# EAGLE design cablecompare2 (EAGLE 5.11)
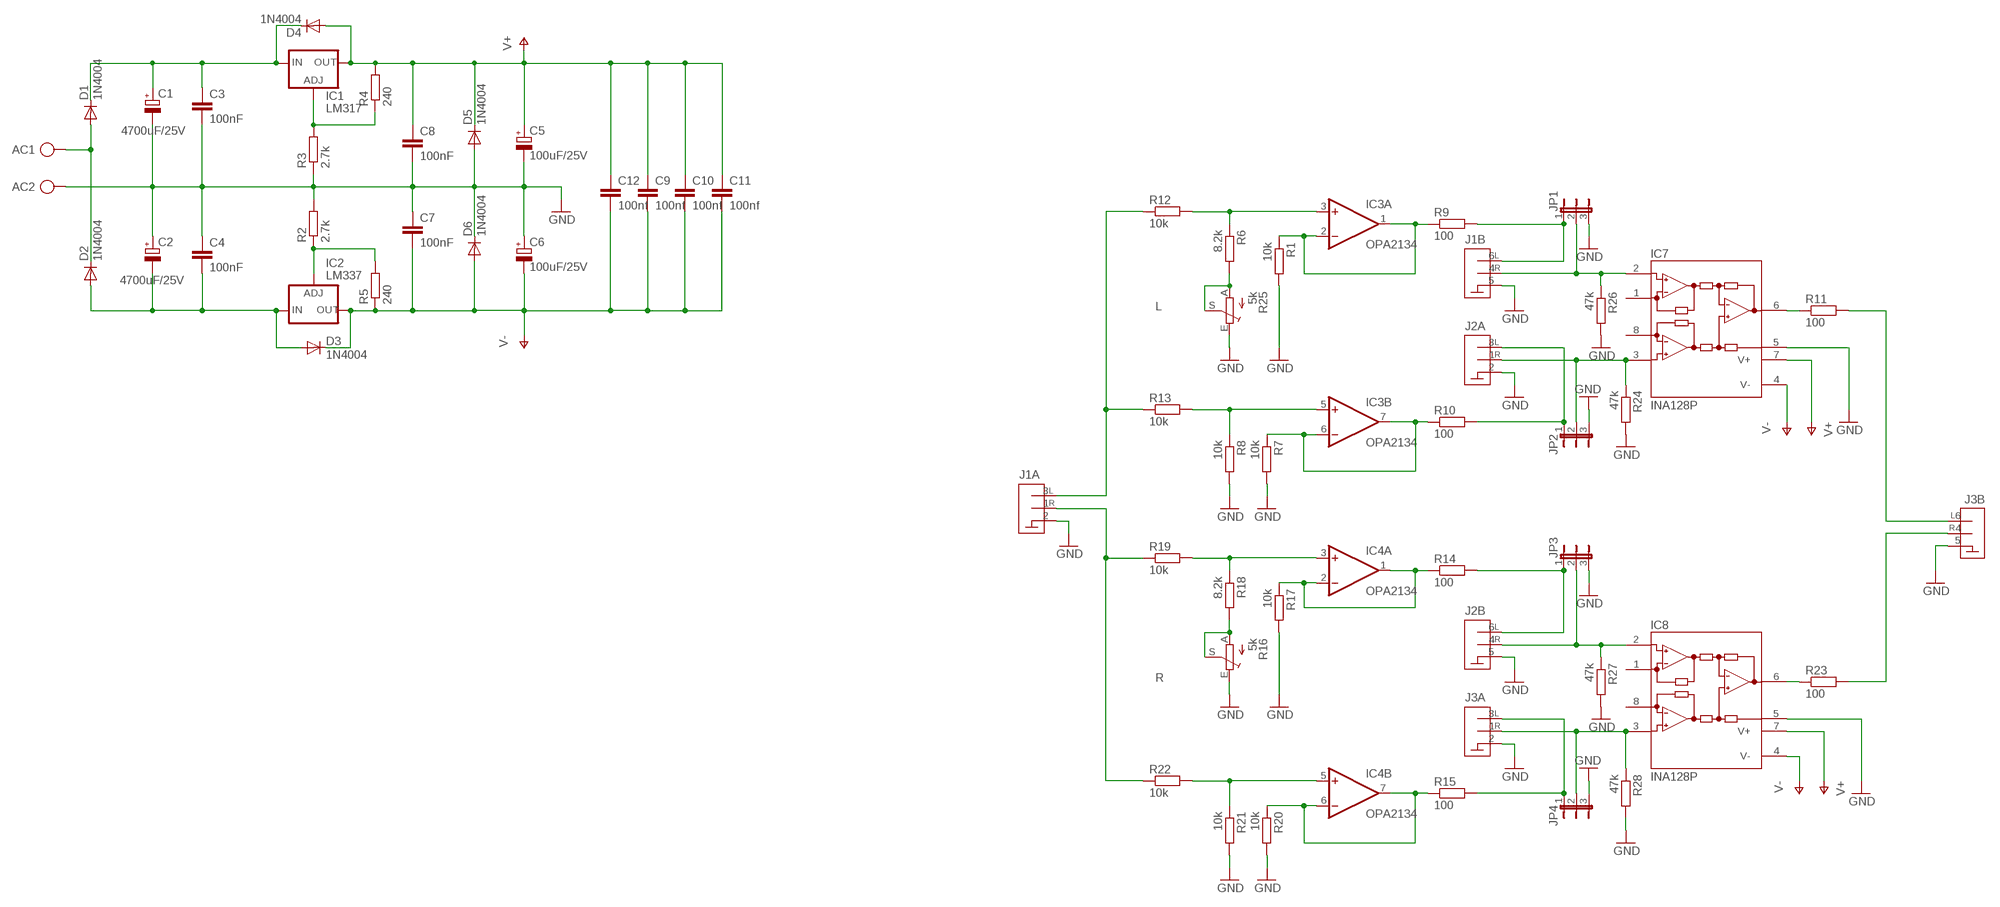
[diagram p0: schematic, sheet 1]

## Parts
AC  ADAPTER-PLUG-5.5MM  [ADAPTER-PLUG-5.5MM]
C1  4700uF/25V  CPOL-EUE7.5-16  [E7,5-16]
C2  4700uF/25V  CPOL-EUE7.5-16  [E7,5-16]
C3  100nF  C-EU050-024X044  [C050-024X044]
C4  100nF  C-EU050-024X044  [C050-024X044]
C5  100uF/25V  CPOL-EUE2.5-6  [E2,5-6]
C6  100uF/25V  CPOL-EUE2.5-6  [E2,5-6]
C7  100nF  C-EU050-024X044  [C050-024X044]
C8  100nF  C-EU050-024X044  [C050-024X044]
C9  100nf  C-EU050-024X044  [C050-024X044]
C10  100nf  C-EU050-024X044  [C050-024X044]
C11  100nf  C-EU050-024X044  [C050-024X044]
C12  100nf  C-EU050-024X044  [C050-024X044]
D1  1N4004  DIODE-DO41-7.6  [DO41-7.6]
D2  1N4004  DIODE-DO41-7.6  [DO41-7.6]
D3  1N4004  DIODE-DO41-7.6  [DO41-7.6]
D4  1N4004  DIODE-DO41-7.6  [DO41-7.6]
D5  1N4004  DIODE-DO41-7.6  [DO41-7.6]
D6  1N4004  DIODE-DO41-7.6  [DO41-7.6]
IC1  LM317  LM317TS  [317TS]
IC2  LM337  LM337TS  [337TS]
IC3  OPA2134  TL072P  [DIL8]
IC4  OPA2134  TL072P  [DIL8]
IC7  INA128P  [DIL08]
IC8  INA128P  [DIL08]
J1  RCA-FEMALE-4  [RCA-4-FEMALE]
J2  RCA-FEMALE-4  [RCA-4-FEMALE]
J3  RCA-FEMALE-4  [RCA-4-FEMALE]
JP1  JP2E  [JP2]
JP2  JP2E  [JP2]
JP3  JP2E  [JP2]
JP4  JP2E  [JP2]
R1  10k  R-EU_0207/10  [0207/10]
R2  2.7k  R-EU_0207/10  [0207/10]
R3  2.7k  R-EU_0207/10  [0207/10]
R4  240  R-EU_0207/10  [0207/10]
R5  240  R-EU_0207/10  [0207/10]
R6  8.2k  R-EU_0207/10  [0207/10]
R7  10k  R-EU_0207/10  [0207/10]
R8  10k  R-EU_0207/10  [0207/10]
R9  100  R-EU_0207/10  [0207/10]
R10  100  R-EU_0207/10  [0207/10]
R11  100  R-EU_0207/10  [0207/10]
R12  10k  R-EU_0207/10  [0207/10]
R13  10k  R-EU_0207/10  [0207/10]
R14  100  R-EU_0207/10  [0207/10]
R15  100  R-EU_0207/10  [0207/10]
R16  5k  TRIM_EU-S64Y  [S64Y]
R17  10k  R-EU_0207/10  [0207/10]
R18  8.2k  R-EU_0207/10  [0207/10]
R19  10k  R-EU_0207/10  [0207/10]
R20  10k  R-EU_0207/10  [0207/10]
R21  10k  R-EU_0207/10  [0207/10]
R22  10k  R-EU_0207/10  [0207/10]
R23  100  R-EU_0207/10  [0207/10]
R24  47k  R-EU_0207/10  [0207/10]
R25  5k  TRIM_EU-S64Y  [S64Y]
R26  47k  R-EU_0207/10  [0207/10]
R27  47k  R-EU_0207/10  [0207/10]
R28  47k  R-EU_0207/10  [0207/10]

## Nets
GND: AC.3 C1.- C2.+ C3.2 C4.1 C5.- C6.+ C7.1 C8.2 D5.A D6.C IC7.5(REF) IC8.5(REF) J1.2(A:GND) J1.5(B:GND) J2.2(A:GND) J2.5(B:GND) J3.2(A:GND) J3.5(B:GND) JP1.3 JP2.3 JP3.3 JP4.3 R1.2 R2.2 R3.1 R7.2 R8.2 R16.E R17.2 R20.2 R21.2 R24.2 R25.E R26.2 R27.2 R28.2
N$1: C1.+ C3.1 D1.C D4.C IC1.3(IN)
N$2: AC.1 D1.A D2.C
N$3: C2.- C4.2 D2.A D3.A IC2.2(IN)
N$4: IC2.1(ADJ) R2.1 R5.2
N$5: IC1.1(ADJ) R3.2 R4.1
N$6: J1.1(A:INR) R19.1 R22.1
N$7: J1.3(A:INL) R12.1 R13.1
N$8: IC3.1(A:OUT) IC3.2(A:-IN) R1.1 R9.1
N$9: J2.3(A:INL) JP2.1 R10.2
N$10: IC7.2(-IN) J1.4(B:INR) JP1.2 R26.1
N$11: IC7.3(+IN) J2.1(A:INR) JP2.2 R24.1
N$12: IC3.6(B:-IN) IC3.7(B:OUT) R7.1 R10.1
N$13: IC3.5(B:+IN) R8.1 R13.2
N$14: IC3.3(A:+IN) R6.1 R12.2
N$15: J1.6(B:INL) JP1.1 R9.2
N$16: IC7.6(OUT) R11.1
N$17: J3.6(B:INL) R11.2
N$18: R6.2 R25.A R25.S
N$19: IC8.2(-IN) J2.4(B:INR) JP3.2 R27.1
N$20: J2.6(B:INL) JP3.1 R14.2
N$21: IC8.3(+IN) J3.1(A:INR) JP4.2 R28.1
N$22: J3.3(A:INL) JP4.1 R15.2
N$25: IC4.1(A:OUT) IC4.2(A:-IN) R14.1 R17.1
N$26: IC4.3(A:+IN) R18.1 R19.2
N$27: R16.A R16.S R18.2
N$28: IC4.6(B:-IN) IC4.7(B:OUT) R15.1 R20.1
N$29: IC4.5(B:+IN) R21.1 R22.2
N$30: IC8.6(OUT) R23.1
N$31: J3.4(B:INR) R23.2
V+: C5.+ C8.1 C9.1 C10.1 C11.1 C12.1 D4.A D5.C IC1.2(OUT) IC7.7(V+) IC8.7(V+) R4.2
V-: C6.- C7.2 C9.2 C10.2 C11.2 C12.2 D3.C D6.A IC2.3(OUT) IC7.4(V-) IC8.4(V-) R5.1
Unconnected: IC7.1(RG) IC7.8(RG) IC8.1(RG) IC8.8(RG)

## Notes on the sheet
- L
- R

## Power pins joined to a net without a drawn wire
V+: IC3.8(P:V+) IC4.8(P:V+)
V-: IC3.4(P:V-) IC4.4(P:V-)

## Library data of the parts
AC = 0000halfgaar:ADAPTER-PLUG-5.5MM: PCB mounted 5.5 mm adapter plug.
C1 C2 C5 C6 = rcl:CPOL-EU: POLARIZED CAPACITOR, European symbol
C3 C4 C7-C12 = rcl:C-EU: CAPACITOR, European symbol
D1-D6 = diode:DIODE-: DIODE
IC1 = v-reg:LM317TS: VOLTAGE REGULATOR
IC2 = v-reg:LM337TS: VOLTAGE REGULATOR
IC3 IC4 = 0000halfgaar:TL072: TL072 dual opamp
IC7 IC8 = burr-brown:INA128: Instrumentation Amplifiers Precision, Low Power; MF: TEXAS INSTRUMENTS; MPN: INA128P; OC_FARNELL: 1212410; OC_NEWARK: 74C9783
J1-J3 = 0000halfgaar:RCA-FEMALE-4: RCA 4 female PCB mount. As bought by okaphone
JP1-JP4 = jumper:JP2E: JUMPER
R1-R15 R17-R24 R26-R28 = rcl:R-EU_: RESISTOR, European symbol
R16 R25 = pot:TRIM_EU-: POTENTIOMETER

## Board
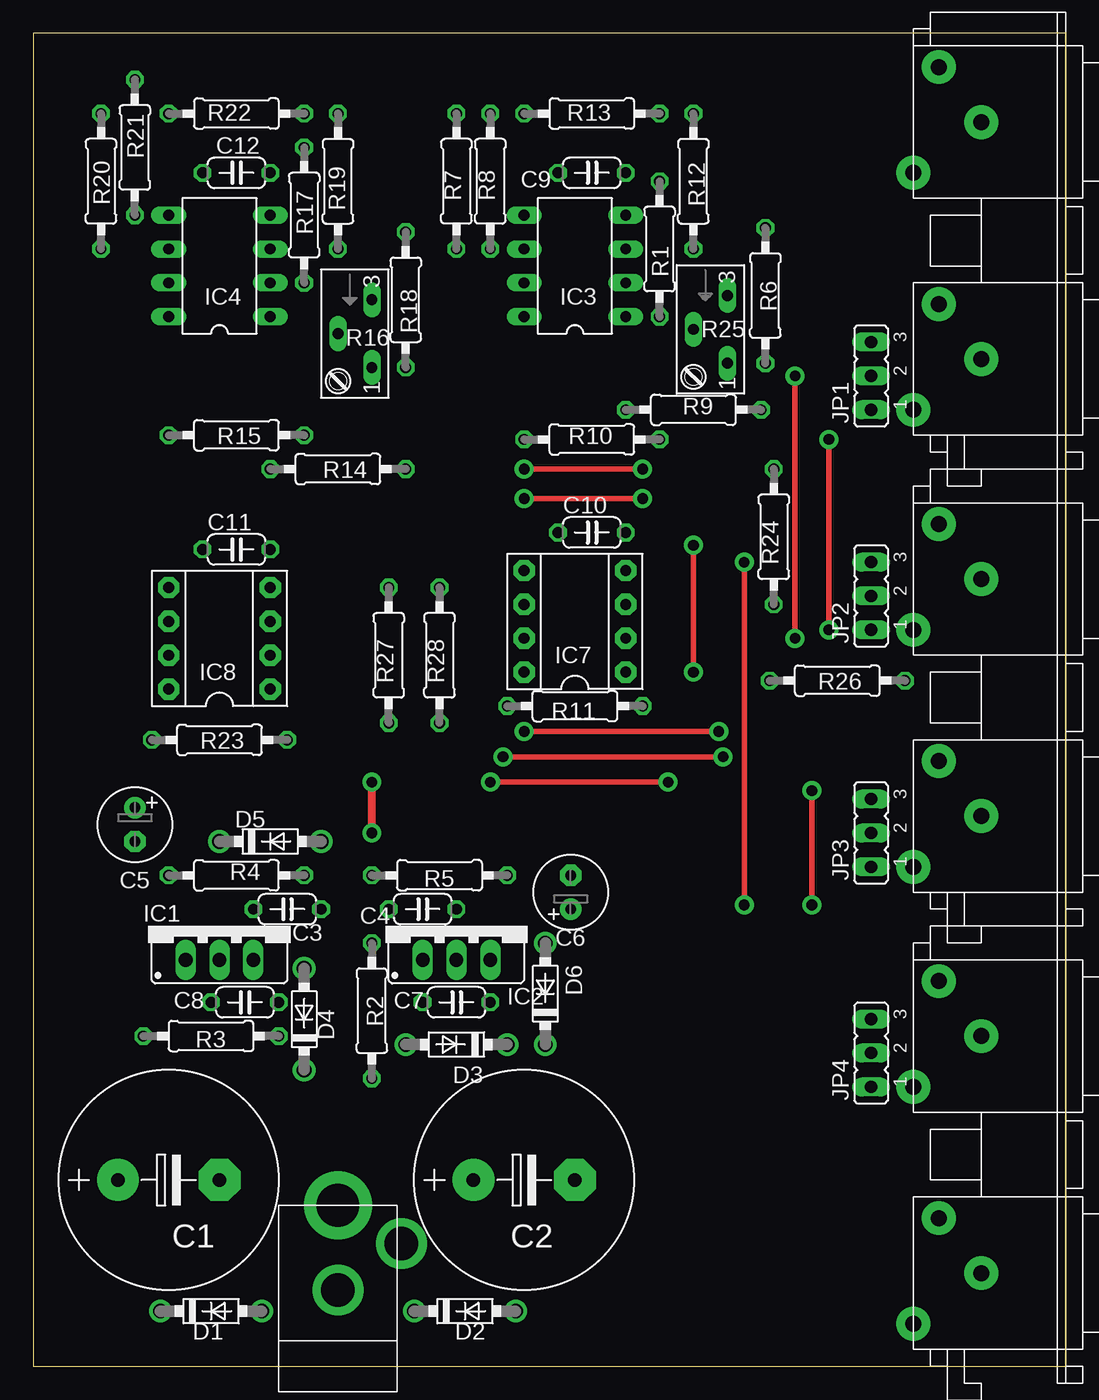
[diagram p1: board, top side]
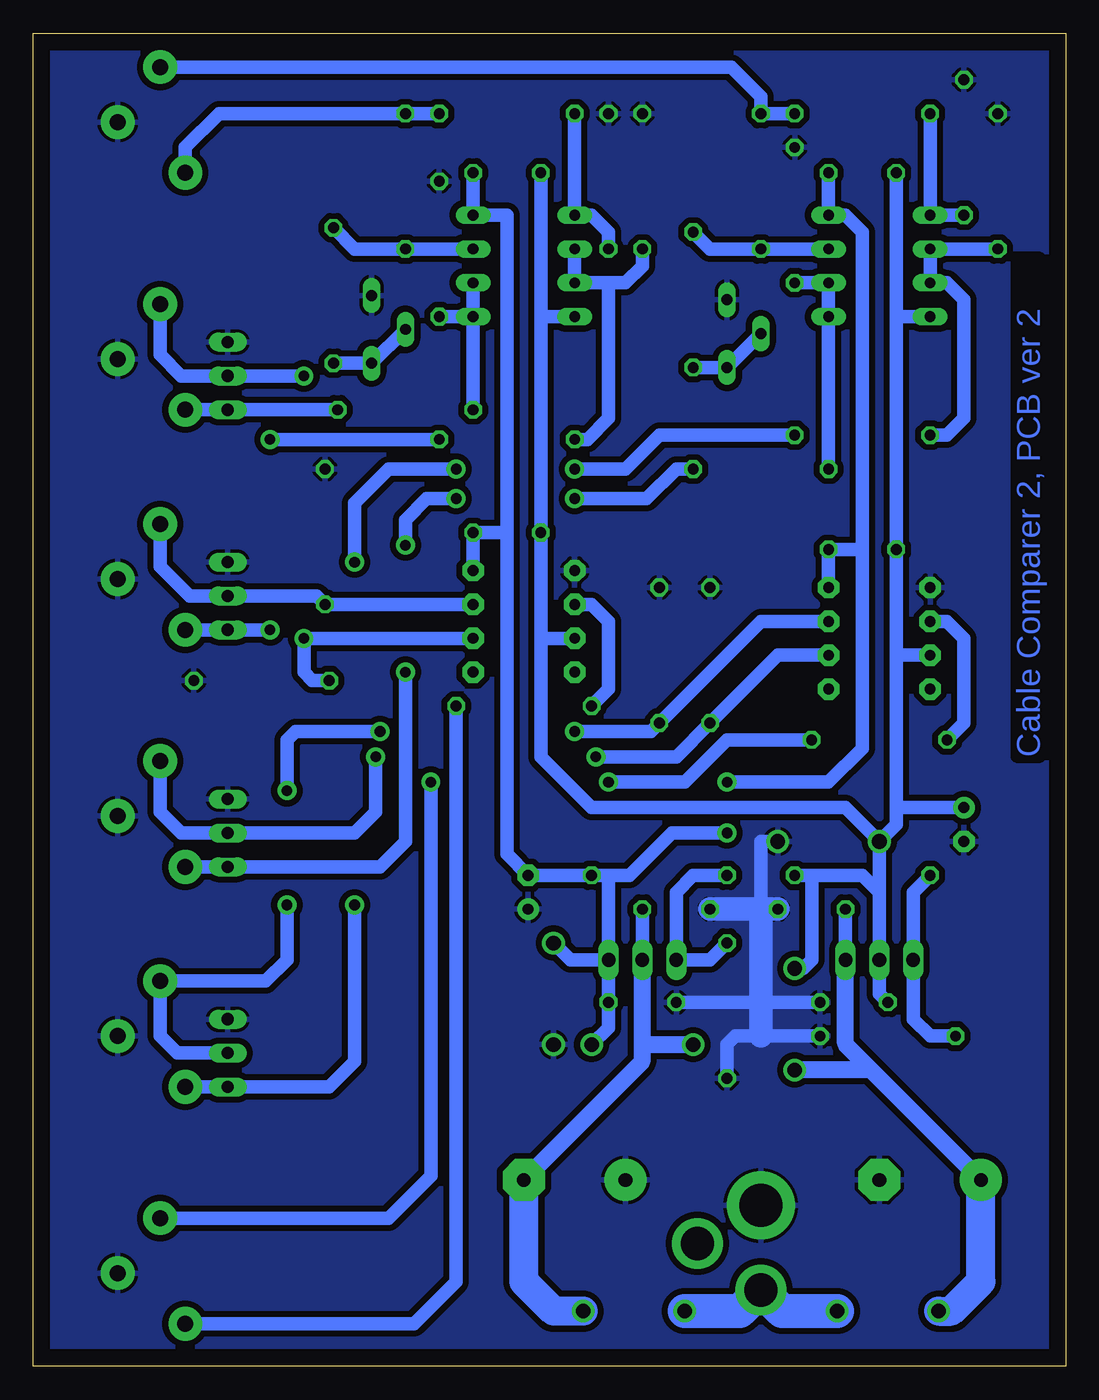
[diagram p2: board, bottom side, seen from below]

Size 77.45 x 100 mm. Coordinates in mm from the lower left corner, seen from the top.
Outline: 0,0 77.45,0 77.45,100 0,100 0,0
Copper layers (1*16): Top 0.035mm / dielectric 1.5mm / Bottom 0.035mm
Design rules "smallsignal *": minimum track width 16mil, minimum drill 31mil, track to track 18mil, track to pad 12mil, pad to pad 20mil, via to via 20mil, smd to smd 8mil, copper to edge 50mil, drill to drill 30mil, minimum pad ring 10mil, minimum via ring 8mil, stop-mask expansion 4mil, vias tented up to drill 0mil, thermal gap 10mil

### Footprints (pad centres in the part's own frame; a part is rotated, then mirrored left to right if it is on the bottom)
ADAPTER-PLUG-5.5MM = drill 2.5 pad 3.81 round: 1 4.445,-7.62; 2 -0.318,-11.113 | drill 3.2 pad 5.08 round: 3 4.445,-13.97
E7,5-16 = drill 1.016 pad 3.15 round: + -3.81,0 | drill 1.016 pad 3.15 octagon: - 3.81,0
C050-024X044 = drill 0.813 octagon: 1 -2.54,0; 2 2.54,0
E2,5-6 = drill 0.813 pad 1.6 round: + -1.27,0 | drill 0.813 pad 1.6 octagon: - 1.27,0
DO41-7.6 = drill 1.1 pad 1.7 round: A 3.81,0; C -3.81,0
317TS = drill 1.016 long: 1 -2.54,-2.54; 2 0,-2.54; 3 2.54,-2.54
337TS = drill 1.016 long: 1 -2.54,-2.54; 2 0,-2.54; 3 2.54,-2.54
DIL8 = drill 0.813 long: 1 -3.81,-3.81; 2 -1.27,-3.81; 3 1.27,-3.81; 4 3.81,-3.81; 5 3.81,3.81; 6 1.27,3.81; 7 -1.27,3.81; 8 -3.81,3.81
DIL08 = drill 0.813 pad 1.6 octagon: 1 -3.81,-3.81; 2 -1.27,-3.81; 3 1.27,-3.81; 4 3.81,-3.81; 5 3.81,3.81; 6 1.27,3.81; 7 -1.27,3.81; 8 -3.81,3.81
RCA-4-FEMALE = drill 1.2 pad 2.54 round: 1 4.128,-10.795; 2 8.255,-7.62; 3 12.065,-12.7; 4 21.907,-10.795; 5 26.035,-7.62; 6 29.845,-12.7
JP2 = drill 0.914 long: 1 -2.54,0; 2 0,0; 3 2.54,0
0207/10 = drill 0.813 octagon: 1 -5.08,0; 2 5.08,0
S64Y = drill 0.813 long: A 2.54,1.27; E -2.54,1.27; S 0,-1.27

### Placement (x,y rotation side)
AC  27.3,-1.91 180 top
C1  10.16,13.97 0 top
C2  36.83,13.97 0 top
C3  19.05,34.29 0 top
C4  29.21,34.29 0 top
C5  7.62,40.64 270 top
C6  40.32,35.56 90 top
C7  31.75,27.3 0 top
C8  15.88,27.3 0 top
C9  41.91,89.53 0 top
C10  41.91,62.55 0 top
C11  15.24,61.28 0 top
C12  15.24,89.53 0 top
D1  13.34,4.13 0 top
D2  32.38,4.13 0 top
D3  31.75,24.13 180 top
D4  20.32,26.04 90 top
D5  17.78,39.37 0 top
D6  38.42,27.94 90 top
IC1  13.97,33.02 0 top
IC2  31.75,33.02 0 top
IC3  40.64,82.55 90 top
IC4  13.97,82.55 90 top
IC7  40.64,55.88 90 top
IC8  13.97,54.61 90 top
J1  78.74,101.6 270 top
J2  78.74,67.31 270 top
J3  78.74,33.02 270 top
JP1  62.87,74.3 90 top
JP2  62.87,57.78 90 top
JP3  62.87,40.01 90 top
JP4  62.87,23.5 90 top
R1  46.99,83.82 90 top
R2  25.4,26.67 270 top
R3  13.34,24.77 180 top
R4  15.24,36.83 0 top
R5  30.48,36.83 180 top
R6  54.93,80.33 270 top
R7  31.75,88.9 90 top
R8  34.29,88.9 90 top
R9  49.53,71.75 0 top
R10  41.91,69.53 0 top
R11  40.64,49.53 0 top
R12  49.53,88.9 270 top
R13  41.91,93.98 180 top
R14  22.86,67.31 0 top
R15  15.24,69.85 0 top
R16  24.13,77.47 270 top
R17  20.32,86.36 90 top
R18  27.94,80.01 270 top
R19  22.86,88.9 270 top
R20  5.08,88.9 90 top
R21  7.62,91.44 90 top
R22  15.24,93.98 180 top
R23  13.97,46.99 0 top
R24  55.56,62.23 90 top
R25  50.8,77.79 270 top
R26  60.33,51.44 0 top
R27  26.67,53.34 90 top
R28  30.48,53.34 90 top

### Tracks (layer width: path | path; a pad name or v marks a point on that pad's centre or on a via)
GND
  Bottom 1.016: R3.1 22.86,24.77 24.77,24.77 25.4,24.13 R2.2 | C8.2 22.86,27.3 C7.1 | 22.86,34.29 22.86,39.37 D5.A
  Bottom 1.778: 22.86,24.77 22.86,27.3 22.86,34.29 | 22.86,34.29 C3.2 | 22.86,34.29 C4.1
  pour Bottom: 0,100.33 0,0 77.47,0 77.47,99.06 77.47,100.33
N$1
  Bottom 1.016: IC1.3 C3.1 | 16.44,24.06 arc45 16.51,24.23
  Bottom 1.27: 16.51,24.23 IC1.3 | C1.+ 14.61,22.23 | 14.61,22.23 16.44,24.06 | 14.61,22.23 D4.C
  Bottom 2.184: D1.C 8.57,4.13 6.35,6.35 C1.+
N$2
  Bottom 2.54: D1.A 21.27,4.13 AC.1 24.45,4.13 D2.C
N$3
  Bottom 1.016: IC2.2 C4.2 | 31.82,22.79 arc-45 31.75,22.96
  Bottom 1.27: 31.75,22.96 31.75,24.13 | 31.75,24.13 IC2.2 | C2.- 31.82,22.79 | 31.75,24.13 D3.A
  Bottom 2.184: D2.A 38.42,4.13 40.64,6.35 C2.-
N$4
  Bottom 1.016: R5.2 27.94,36.83 29.21,35.56 IC2.1 26.77,30.48 arc-45 26.6,30.55 R2.1
N$5
  Bottom 1.016: R4.1 11.43,35.56 IC1.1 11.43,26.04 10.16,24.77 R3.2
N$6
  Bottom 1.016: R22.1 R19.1 22.86,95.25 25.08,97.47 J1.1
N$7
  Bottom 1.016: R13.1 R12.1 63.5,93.98 66.04,91.44 J1.3
N$8
  Bottom 1.016: IC3.1 IC3.2 | IC3.1 R1.1 | R9.1 IC3.1
N$9  (via drill 0.8 pad 1.42)
  Top 0.406: v59.69,55.24 v59.69,69.53
  Bottom 1.016: J2.3 JP2.1 v59.69,55.24 | v59.69,69.53 R10.2
N$10  (via drill 0.8 pad 1.42)
  Top 0.406: v57.15,54.61 v57.15,74.3
  Bottom 1.016: J1.4 67.94,75.88 66.36,74.3 JP1.2 v57.15,74.3 | IC7.2 v57.15,54.61 57.15,52.07 56.52,51.44 R26.1
N$11
  Bottom 1.016: J2.1 67.94,60.01 65.72,57.78 JP2.2 56.2,57.78 R24.1 IC7.3
N$12
  Bottom 1.016: IC3.6 IC3.7 34.29,81.28 | R7.1 31.75,82.55 33.02,81.28 34.29,81.28 | R10.1 35.88,69.53 34.29,71.12 34.29,81.28
N$13
  Bottom 1.016: R13.2 IC3.5 35.56,86.36 34.29,85.09 R8.1
N$14
  Bottom 1.016: IC3.3 R12.2 53.34,83.82 R6.1
N$15
  Bottom 1.016: J1.6 JP1.1 R9.2
N$16
  Bottom 1.016: R11.1 34.29,50.8 34.29,55.88 35.56,57.15 IC7.6
N$17
  Bottom 1.016: J3.6 48.9,3.17 45.72,6.35 R11.2
N$18
  Bottom 1.016: R25.S R25.A R6.2
N$19  (via drill 0.8 pad 1.42)
  Top 0.406: v35.24,45.72 v51.75,45.72
  Bottom 1.016: J2.4 67.94,41.59 66.36,40.01 JP3.2 53.34,40.01 51.75,41.59 v51.75,45.72 | IC8.2 21.59,53.34 R27.1 29.21,45.72 v35.24,45.72
N$20  (via drill 0.8 pad 1.42)
  Top 0.406: v45.72,65.09 v36.83,65.09 | v49.53,52.07 v49.53,61.59
  Bottom 1.016: J2.6 JP3.1 51.44,37.47 49.53,39.37 v49.53,52.07 | R14.2 29.21,67.31 31.43,65.09 v36.83,65.09 | v45.72,65.09 47.94,65.09 49.53,63.5 v49.53,61.59
N$21  (via drill 0.8 pad 1.42)
  Top 0.406: v36.83,47.62 v51.44,47.62 | v58.42,43.18 v58.42,34.61
  Bottom 1.016: JP4.2 66.67,23.5 67.94,24.77 J3.1 60.01,28.89 58.42,30.48 v58.42,34.61 | IC8.3 22.86,55.88 R28.1 31.11,47.62 v36.83,47.62 | v51.44,47.62 57.78,47.62 58.42,46.99 v58.42,43.18
N$22  (via drill 0.8 pad 1.42)
  Top 0.406: v45.72,67.31 v36.83,67.31 | v53.34,34.61 v53.34,60.33
  Bottom 1.016: J3.3 JP4.1 55.24,20.95 53.34,22.86 v53.34,34.61 | R15.2 30.48,69.85 33.02,67.31 v36.83,67.31 | v45.72,67.31 50.8,67.31 53.34,64.77 v53.34,60.33
N$25
  Bottom 1.016: R17.1 IC4.2 IC4.1 R14.1
N$26
  Bottom 1.016: IC4.3 R19.2 26.67,83.82 R18.1
N$27
  Bottom 1.016: R16.S R16.A R18.2
N$28
  Bottom 1.016: R20.1 IC4.6 IC4.7 8.89,81.28 7.62,80.01 7.62,71.12 8.89,69.85 R15.1
N$29
  Bottom 1.016: R21.1 IC4.5 R22.2
N$30
  Bottom 1.016: R23.1 7.62,48.26 7.62,54.61 8.89,55.88 IC8.6
N$31  (via drill 0.8 pad 1.42)
  Top 0.406: v47.62,43.81 v34.29,43.81
  Bottom 1.016: R23.2 25.4,46.99 28.57,43.81 v34.29,43.81 | J3.4 50.8,11.11 47.62,14.29 v47.62,43.81
V+
  Bottom 1.016: 19.05,36.83 15.24,36.83 13.97,35.56 | 19.05,36.83 R4.2 | 13.97,35.56 IC1.2 13.97,27.94 C8.1 | 13.97,35.56 D5.C | D4.A 19.79,29.84 arc-45 19.61,29.92 19.05,30.48 19.05,36.83 | 39.37,78.74 C10.1 39.37,54.61 | 39.37,78.74 C9.1 | 39.37,54.61 IC7.7 | 12.7,78.74 C11.1 12.7,53.34 | 12.7,78.74 C12.1 | 12.7,78.74 IC4.8 | 12.7,53.34 IC8.7 | 39.37,78.74 IC3.8 | D5.C 12.7,40.64 12.7,41.91 | 12.7,41.91 12.7,53.34 | 12.7,41.91 C5.+ | 39.37,54.61 39.37,45.72 35.56,41.91 16.51,41.91 D5.C
V-  (via drill 0.8 pad 1.42)
  Top 0.61: v25.4,40.01 v25.4,43.81
  Bottom 1.016: IC2.3 C7.2 34.29,25.4 D3.C | C9.2 IC3.4 41.91,86.36 41.91,62.55 | 41.91,62.55 C10.2 IC7.4 | C12.2 IC4.4 16.51,86.36 15.24,85.09 15.24,61.28 | 15.24,61.28 15.24,46.35 17.78,43.81 v25.4,43.81 | 15.24,61.28 C11.2 IC8.4 | 41.91,62.55 41.91,38.42 C6.- R5.1 34.29,36.83 | 34.29,36.83 32.7,36.83 29.53,40.01 v25.4,40.01 | IC2.3 34.29,36.83 | IC2.3 37.15,30.48 D6.A

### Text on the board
Bottom: Cable Comparer 2, PCB ver 2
